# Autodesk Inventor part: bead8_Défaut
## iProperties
Shininess: 64.0
Length Units: 11269
Angle Units: 11279
Time Units: 11290
Mass Units: 11283
Length Display Precision: 3
Angle Display Precision: 2
Compacted: True
Part Number: bead8_Défaut
Document SubType Name: Modeling
Created: 2006-01
Material: Par défaut
Designer: Fricot
Density: 0.0
Volumn: 0.0
Area: 0.0
PropertySet Name: Model Information
Control State: 0
Master: False
Checked Out: False
Author: Fricot
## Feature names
1. Base1
